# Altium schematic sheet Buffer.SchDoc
size A4
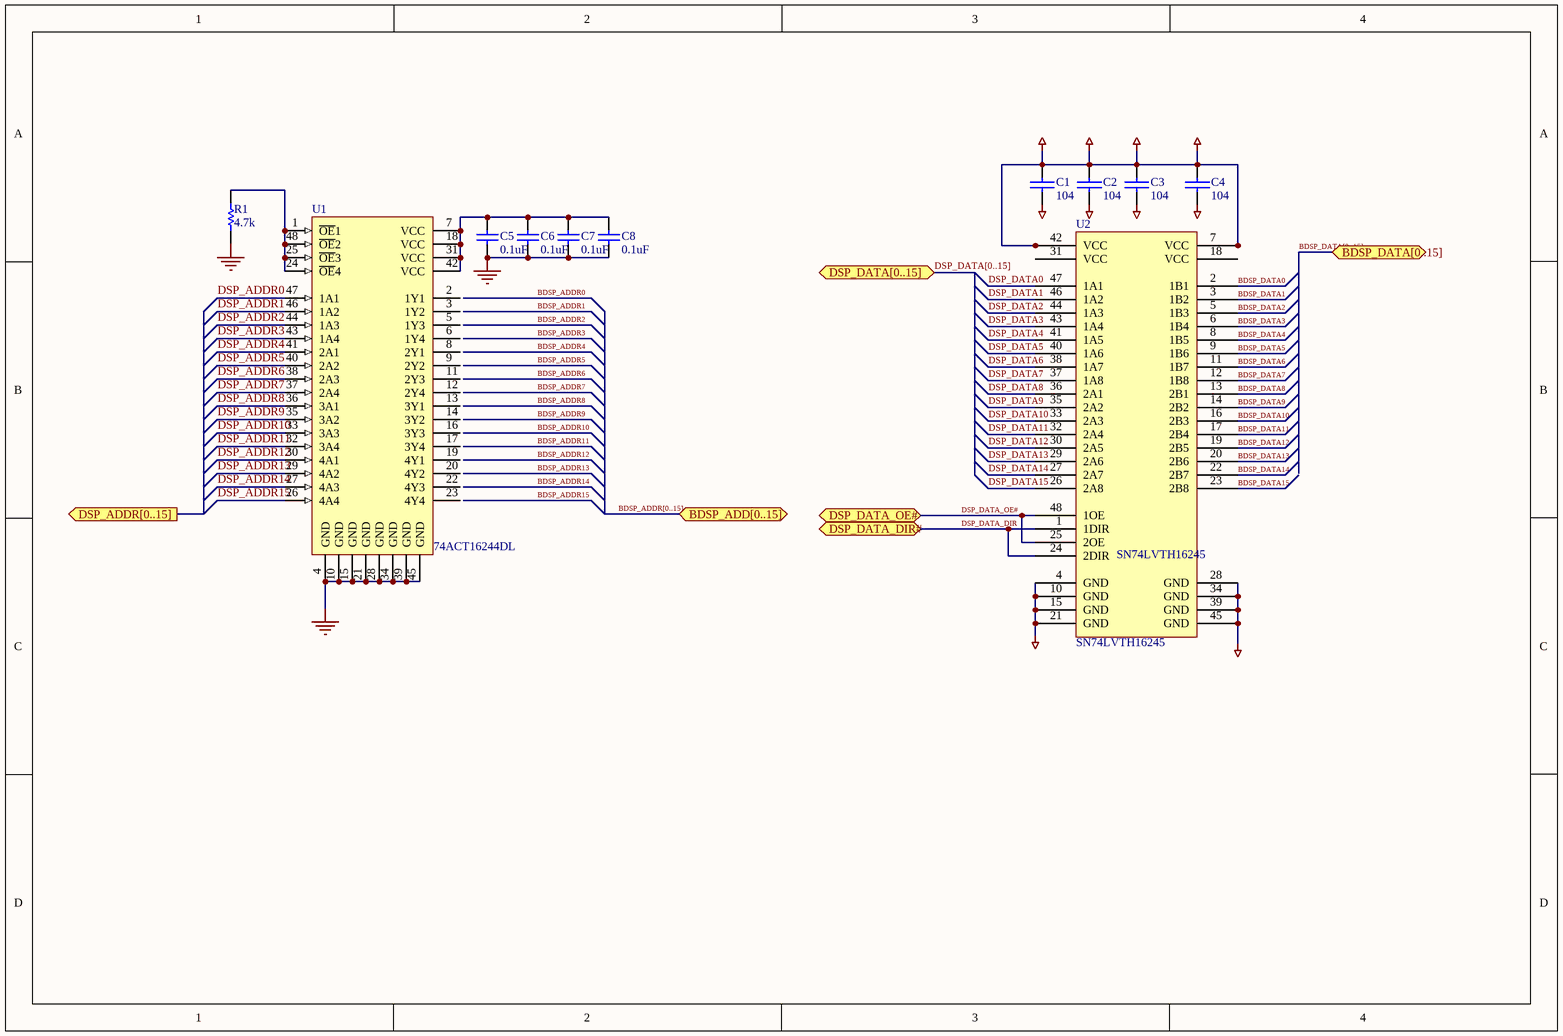
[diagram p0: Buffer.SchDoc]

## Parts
C1  104  [0805]
C2  104  [0805]
C3  104  [0805]
C4  104  [0805]
C5  0.1uF  [RAD-0.3]
C6  0.1uF  [RAD-0.3]
C7  0.1uF  [RAD-0.3]
C8  0.1uF  [RAD-0.3]
R1  4.7k  [AXIAL-0.3]
U1  74ACT16244DL  [SSO-G48]
U2  SN74LVTH16245  [TSOP48]

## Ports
BDSP_ADD[0..15], BDSP_DATA[0..15], DSP_ADDR[0..15] (out), DSP_DATA[0..15], DSP_DATA_DIR#, DSP_DATA_OE#

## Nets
3.3V: C1.1 C2.1 C3.1 C4.1 U2.7(VCC) U2.42(VCC)
DGND: C1.2 C2.2 C3.2 C4.2 U2.4(GND) U2.10(GND) U2.15(GND) U2.21(GND) U2.28(GND) U2.34(GND) U2.39(GND) U2.45(GND)
GND: C5.1 C6.1 C7.1 C8.1 R1.1 U1.4(GND) U1.10(GND) U1.15(GND) U1.21(GND) U1.28(GND) U1.34(GND) U1.39(GND) U1.45(GND)
BDSP_DATA0: U2.2(1B1)
BDSP_DATA1: U2.3(1B2)
BDSP_DATA2: U2.5(1B3)
BDSP_DATA3: U2.6(1B4)
BDSP_DATA4: U2.8(1B5)
BDSP_DATA5: U2.9(1B6)
BDSP_DATA6: U2.11(1B7)
BDSP_DATA7: U2.12(1B8)
BDSP_DATA8: U2.13(2B1)
BDSP_DATA9: U2.14(2B2)
BDSP_DATA10: U2.16(2B3)
BDSP_DATA11: U2.17(2B4)
BDSP_DATA12: U2.19(2B5)
BDSP_DATA13: U2.20(2B6)
BDSP_DATA14: U2.22(2B7)
BDSP_DATA15: U2.23(2B8)
DSP_ADDR0: U1.47(1A1)
DSP_ADDR1: U1.46(1A2)
DSP_ADDR2: U1.44(1A3)
DSP_ADDR3: U1.43(1A4)
DSP_ADDR4: U1.41(2A1)
DSP_ADDR5: U1.40(2A2)
DSP_ADDR6: U1.38(2A3)
DSP_ADDR7: U1.37(2A4)
DSP_ADDR8: U1.36(3A1)
DSP_ADDR9: U1.35(3A2)
DSP_ADDR10: U1.33(3A3)
DSP_ADDR11: U1.32(3A4)
DSP_ADDR12: U1.30(4A1)
DSP_ADDR13: U1.29(4A2)
DSP_ADDR14: U1.27(4A3)
DSP_ADDR15: U1.26(4A4)
DSP_DATA0: U2.47(1A1)
DSP_DATA1: U2.46(1A2)
DSP_DATA2: U2.44(1A3)
DSP_DATA3: U2.43(1A4)
DSP_DATA4: U2.41(1A5)
DSP_DATA5: U2.40(1A6)
DSP_DATA6: U2.38(1A7)
DSP_DATA7: U2.37(1A8)
DSP_DATA8: U2.36(2A1)
DSP_DATA9: U2.35(2A2)
DSP_DATA10: U2.33(2A3)
DSP_DATA11: U2.32(2A4)
DSP_DATA12: U2.30(2A5)
DSP_DATA13: U2.29(2A6)
DSP_DATA14: U2.27(2A7)
DSP_DATA15: U2.26(2A8)
DSP_DATA_DIR: U2.1(1DIR) U2.24(2DIR) ; port DSP_DATA_DIR#
DSP_DATA_OE#: U2.25(2OE) U2.48(1OE) ; port DSP_DATA_OE#
NetC5_2: C5.2 C6.2 C7.2 C8.2 U1.7(VCC) U1.18(VCC) U1.31(VCC) U1.42(VCC)
NetR1_2: R1.2 U1.1(~{OE}1) U1.24(~{OE}4) U1.25(~{OE}3) U1.48(~{OE}2)

Not connected (* = marked no-connect by the designer): U1 2(1Y1) 3(1Y2) 5(1Y3) 6(1Y4) 8(2Y1) 9(2Y2) 11(2Y3) 12(2Y4) 13(3Y1) 14(3Y2) 16(3Y3) 17(3Y4) 19(4Y1) 20(4Y2) 22(4Y3) 23(4Y4); U2 18(VCC) 31(VCC)

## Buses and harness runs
bus BDSP_ADDR[0..15] = port BDSP_ADD[0..15]
bus BDSP_DATA[0..15] = port BDSP_DATA[0..15]
bus DSP_DATA[0..15] = port DSP_DATA[0..15]

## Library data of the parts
C1-C4 = CAP: Capacitor
C5-C8 = Cap: Capacitor; Manufacturer: Generic Components; Class I: Passive; Value: 100pF
R1 = Res1: Resistor; Manufacturer: Generic Components; Class I: Passive; Value: 1K
U1 = 74ACT16244DL: 16-Bit Buffer/Line Driver with 3-State Outputs; Manufacturer: Texas Instruments; Package Information: Latest Revision: Jan-1998; Class I: Logic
